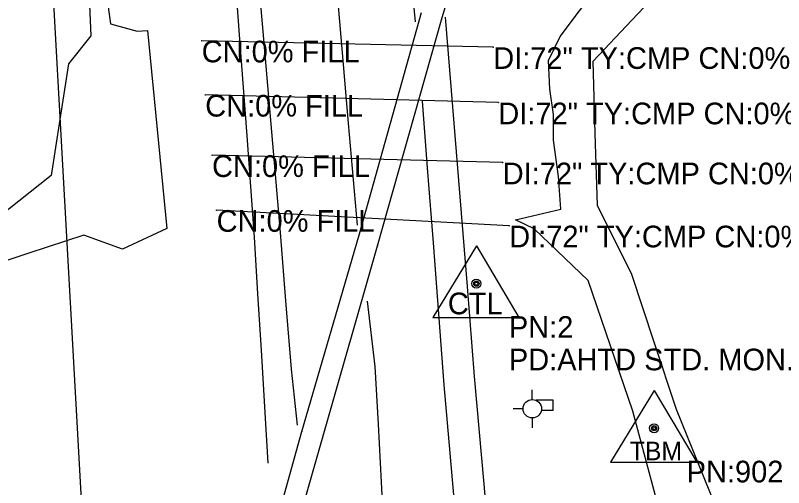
# Model space of a CAD drawing. Extents: x 929765 to 934279, y 1533086 to 1541189.
# Drawn here: x 931934.2 to 932111.4, y 1537318.7 to 1537427.6 of the extents above; entities that cross this region are included whole.
import ezdxf

# ---------------------------------------------------------------- set-up
doc = ezdxf.new("R2010")
doc.units = 0
for name, color, linetype in [('S_CROSS_DRAIN', 7, 'Continuous'), ('S_CROSS_DRAIN_ANNOT', 7, 'Continuous'), ('S_DITCHLINE', 7, 'Continuous'), ('S_DRG_PT_SYM', 7, 'Continuous'), ('S_EDGE_PAVEMENT', 7, 'Continuous'), ('S_MSC_PT_SYM', 7, 'Continuous'), ('S_PAVEMENT_CROWN', 7, 'Continuous'), ('S_PRIMARY_CTL', 7, 'Continuous'), ('S_PRIMARY_CTL_ANNOT', 7, 'Continuous'), ('S_RAILROAD', 7, 'Continuous'), ('S_SANITARY_SEWER', 7, 'Continuous'), ('S_SHOULDER', 7, 'Continuous')]:
    doc.layers.add(name, color=color, linetype=linetype)

msp = doc.modelspace()

# ---------------------------------------------------------------- linework, layer by layer
at = {"layer": 'S_CROSS_DRAIN'}
for p, q in [((932044.4, 1537420.25), (931977.17, 1537421.75)), ((932045.58, 1537407.47), (931977.98, 1537409.25)), ((932046.59, 1537393.62), (931979.56, 1537395.31)), ((932048.08, 1537379.08), (931980.61, 1537382.67))]:
    msp.add_line(p, q, dxfattribs=at)
at = {"layer": 'S_DITCHLINE'}
for points in [[(932085.78, 1537301.84), (932081.18, 1537319.05), (932076.57, 1537336.26), (932071.43, 1537351.35), (932066.29, 1537366.45), (932053.86, 1537378.37), (932049.5, 1537380.42), (932059.98, 1537382.88), (932059.48, 1537390.45), (932058.32, 1537398.79), (932058.33, 1537404.72), (932057.44, 1537410.6), (932057.14, 1537417.22), (932059.87, 1537422.73), (932068.73, 1537434.65), (932077.6, 1537446.56), (932085.12, 1537457.75), (932092.64, 1537468.94), (932092.11, 1537482.59), (932096.23, 1537495.57), (932101.45, 1537495.39), (932102.69, 1537491.18), (932106.29, 1537496.21)], [(932126.62, 1537258.44), (932108.91, 1537270.62), (932105.45, 1537284.68), (932101.98, 1537298.75), (932094.32, 1537317.71), (932086.66, 1537336.67), (932081.51, 1537352.24), (932076.37, 1537367.8), (932068.43, 1537383.73), (932067.92, 1537400.37), (932067.42, 1537417), (932077.7, 1537427.87), (932087.98, 1537438.73), (932101.66, 1537459.25), (932108.63, 1537471.21), (932115.61, 1537483.17), (932113.54, 1537495.88)], [(931960.73, 1537473.11), (931955.67, 1537459.62), (931950.61, 1537446.13), (931951.63, 1537422.85), (931946.42, 1537416.45), (931944.44, 1537403.55), (931942.46, 1537390.65), (931930.06, 1537380.86), (931917.67, 1537371.06), (931905.8, 1537349.22), (931891.3, 1537336.47)], [(931964.13, 1537470.78), (931958.69, 1537458.85), (931953.25, 1537446.93), (931956.11, 1537425.64), (931962.3, 1537423.93), (931964.69, 1537424.11), (931966.9, 1537401.27), (931969.1, 1537378.44), (931958.88, 1537373.67), (931949.96, 1537376.9), (931937.32, 1537372.75), (931924.68, 1537368.59), (931916.88, 1537353.63), (931909.08, 1537338.66), (931901.6, 1537326.5), (931894.11, 1537314.34), (931873.82, 1537300.85), (931853.53, 1537287.36), (931835.12, 1537272.97), (931824.41, 1537264.81), (931813.7, 1537256.65), (931802.99, 1537248.49), (931792.29, 1537240.33), (931772.04, 1537229.23)]]:
    msp.add_lwpolyline(points, dxfattribs=at)
at = {"layer": 'S_DRG_PT_SYM'}
for points in [[(931977.17, 1537421.75), (931977.17, 1537421.8), (931977.17, 1537421.75), (931977.12, 1537421.75), (931977.17, 1537421.75), (931977.17, 1537421.7), (931977.17, 1537421.75), (931977.22, 1537421.75)], [(932044.4, 1537420.25), (932044.4, 1537420.3), (932044.4, 1537420.25), (932044.35, 1537420.25), (932044.4, 1537420.25), (932044.4, 1537420.2), (932044.4, 1537420.25), (932044.45, 1537420.25)], [(931977.98, 1537409.25), (931977.98, 1537409.3), (931977.98, 1537409.25), (931977.93, 1537409.25), (931977.98, 1537409.25), (931977.98, 1537409.2), (931977.98, 1537409.25), (931978.03, 1537409.25)], [(932045.58, 1537407.47), (932045.58, 1537407.52), (932045.58, 1537407.47), (932045.53, 1537407.47), (932045.58, 1537407.47), (932045.58, 1537407.42), (932045.58, 1537407.47), (932045.63, 1537407.47)], [(931979.56, 1537395.31), (931979.56, 1537395.36), (931979.56, 1537395.31), (931979.51, 1537395.31), (931979.56, 1537395.31), (931979.56, 1537395.26), (931979.56, 1537395.31), (931979.61, 1537395.31)], [(932046.59, 1537393.62), (932046.59, 1537393.67), (932046.59, 1537393.62), (932046.54, 1537393.62), (932046.59, 1537393.62), (932046.59, 1537393.57), (932046.59, 1537393.62), (932046.64, 1537393.62)], [(931980.61, 1537382.67), (931980.61, 1537382.72), (931980.61, 1537382.67), (931980.56, 1537382.67), (931980.61, 1537382.67), (931980.61, 1537382.62), (931980.61, 1537382.67), (931980.66, 1537382.67)], [(932048.08, 1537379.08), (932048.08, 1537379.13), (932048.08, 1537379.08), (932048.03, 1537379.08), (932048.08, 1537379.08), (932048.08, 1537379.03), (932048.08, 1537379.08), (932048.13, 1537379.08)]]:
    msp.add_lwpolyline(points, dxfattribs=at)
at = {"layer": 'S_EDGE_PAVEMENT'}
for points in [[(931999.26, 1537333.05), (931997.86, 1537345.98), (931996.59, 1537361.76), (931995.32, 1537377.53), (931993.34, 1537400.7), (931991.36, 1537423.88), (931989.38, 1537447.05), (931987.39, 1537470.22), (931985.33, 1537491.8), (931983.28, 1537513.38), (931981.22, 1537534.96), (931979.16, 1537556.54)], [(932026.51, 1537426.11), (932024.2, 1537450.08), (932021.89, 1537474.04), (932020.58, 1537486.58), (932019.27, 1537499.11), (932019.09, 1537507.16)], [(932059.21, 1537034.36), (932058.05, 1537048.52), (932056.89, 1537062.69), (932055.72, 1537076.85), (932054.56, 1537091.01), (932053.08, 1537108.03), (932051.6, 1537125.05), (932050.12, 1537142.07), (932048.64, 1537159.08), (932046.94, 1537178.95), (932045.24, 1537198.83), (932043.54, 1537218.7), (932041.84, 1537238.57), (932040.71, 1537252.26), (932039.58, 1537265.94), (932038.44, 1537279.63), (932037.31, 1537293.31), (932035.21, 1537317.83), (932033.1, 1537342.36), (932031.84, 1537358.72), (932030.59, 1537375.09), (932029.34, 1537391.46), (932028.08, 1537407.83)]]:
    msp.add_lwpolyline(points, dxfattribs=at)
at = {"layer": 'S_MSC_PT_SYM'}
for points in [[(932032.49, 1537426.55), (932032.49, 1537426.6), (932032.49, 1537426.55), (932032.44, 1537426.55), (932032.49, 1537426.55), (932032.49, 1537426.5), (932032.49, 1537426.55), (932032.54, 1537426.55)], [(932013.4, 1537376.69), (932013.4, 1537376.74), (932013.4, 1537376.69), (932013.35, 1537376.69), (932013.4, 1537376.69), (932013.4, 1537376.64), (932013.4, 1537376.69), (932013.45, 1537376.69)], [(932017.74, 1537374.41), (932017.74, 1537374.46), (932017.74, 1537374.41), (932017.69, 1537374.41), (932017.74, 1537374.41), (932017.74, 1537374.36), (932017.74, 1537374.41), (932017.79, 1537374.41)], [(932000.29, 1537331.57), (932000.29, 1537331.62), (932000.29, 1537331.57), (932000.24, 1537331.57), (932000.29, 1537331.57), (932000.29, 1537331.52), (932000.29, 1537331.57), (932000.34, 1537331.57)], [(932005.02, 1537330.1), (932005.02, 1537330.15), (932005.02, 1537330.1), (932004.97, 1537330.1), (932005.02, 1537330.1), (932005.02, 1537330.05), (932005.02, 1537330.1), (932005.07, 1537330.1)]]:
    msp.add_lwpolyline(points, dxfattribs=at)
at = {"layer": 'S_PAVEMENT_CROWN'}
for points in [[(932013.1, 1537379.23), (932011.05, 1537402.7), (932008.99, 1537426.17), (932006.94, 1537449.63), (932004.88, 1537473.1), (932002.67, 1537494.31), (932000.45, 1537515.52), (931998.24, 1537536.73), (931996.02, 1537557.94)], [(932041.76, 1537037.1), (932040.61, 1537050.43), (932039.45, 1537063.77), (932038.3, 1537077.1), (932037.14, 1537090.44), (932035.75, 1537107.51), (932034.36, 1537124.59), (932032.97, 1537141.66), (932031.58, 1537158.74), (932029.79, 1537178.36), (932027.99, 1537197.98), (932026.19, 1537217.6), (932024.39, 1537237.22), (932023.31, 1537251.24), (932022.23, 1537265.26), (932021.15, 1537279.28), (932020.07, 1537293.3), (932019.35, 1537306.62), (932018.64, 1537319.95), (932017.92, 1537333.27), (932017.2, 1537346.6), (932015.42, 1537361.67)]]:
    msp.add_lwpolyline(points, dxfattribs=at)
at = {"layer": 'S_PRIMARY_CTL'}
for p, q in [((932040.51, 1537374.41), (932030.48, 1537357.9)), ((932040.51, 1537374.41), (932050.34, 1537357.9)), ((932030.48, 1537357.9), (932050.34, 1537357.9)), ((932081.51, 1537341.06), (932071.48, 1537324.54)), ((932081.51, 1537341.06), (932091.33, 1537324.54)), ((932071.48, 1537324.54), (932091.33, 1537324.54))]:
    msp.add_line(p, q, dxfattribs=at)
for centre, radius in [((932040.51, 1537365.71), 1.04), ((932040.51, 1537365.71), 0.609), ((932040.51, 1537365.71), 0.344), ((932081.51, 1537332.36), 1.04), ((932081.51, 1537332.36), 0.609), ((932081.51, 1537332.36), 0.344)]:
    msp.add_circle(centre, radius, dxfattribs=at)
at = {"layer": 'S_RAILROAD'}
for p, q in [((932032.49, 1537426.55), (932048.31, 1537482.23)), ((932013.4, 1537376.69), (932027.87, 1537428.26)), ((932017.74, 1537374.41), (932032.49, 1537426.55)), ((932000.29, 1537331.57), (932013.4, 1537376.69)), ((932005.02, 1537330.1), (932017.74, 1537374.41)), ((932053.4, 1537338.96), (932053.4, 1537341.21)), ((932058.21, 1537338.8), (932054.33, 1537338.8)), ((932058.21, 1537336.48), (932058.21, 1537338.8)), ((932051.31, 1537336.83), (932048.99, 1537336.83)), ((932058.21, 1537336.48), (932055.5, 1537336.48)), ((932053.48, 1537332.41), (932053.48, 1537334.73)), ((931989.67, 1537294.03), (932000.29, 1537331.57)), ((931994.39, 1537292.75), (932005.02, 1537330.1))]:
    msp.add_line(p, q, dxfattribs=at)
msp.add_circle((932053.41, 1537336.85), 2.13, dxfattribs=at)
at = {"layer": 'S_SANITARY_SEWER'}
msp.add_line((931950.77, 1537292.06), (931940.09, 1537483.33), dxfattribs=at)
at = {"layer": 'S_SHOULDER'}
for points in [[(931992.49, 1537324.27), (931991.71, 1537337.31), (931990.93, 1537350.35), (931990.15, 1537363.39), (931989.37, 1537376.43), (931987.64, 1537399.77), (931985.9, 1537423.12), (931984.16, 1537446.46), (931982.42, 1537469.81), (931981.22, 1537485.1), (931980.01, 1537500.39), (931979.72, 1537501.28)], [(932065.34, 1537035.86), (932064.27, 1537049.8), (932063.21, 1537063.74), (932062.14, 1537077.68), (932061.08, 1537091.63), (932059.66, 1537108.77), (932058.23, 1537125.91), (932056.81, 1537143.06), (932055.39, 1537160.2), (932053.73, 1537179.84), (932052.07, 1537199.48), (932050.41, 1537219.11), (932048.75, 1537238.75), (932047.67, 1537252.72), (932046.6, 1537266.7), (932045.52, 1537280.67), (932044.45, 1537294.64), (932042.28, 1537319.47), (932040.11, 1537344.3), (932038.43, 1537365.02), (932036.75, 1537385.74), (932035.07, 1537406.47), (932033.39, 1537427.19)]]:
    msp.add_lwpolyline(points, dxfattribs=at)

# ---------------------------------------------------------------- texts
at = {"layer": 'S_CROSS_DRAIN_ANNOT'}
for s, p in [('CN:0% FILL', (931977.17, 1537416.75)), ('DI:72" TY:CMP CN:0% FILL LN:67\'', (932044.4, 1537415.25)), ('CN:0% FILL', (931977.98, 1537404.25)), ('DI:72" TY:CMP CN:0% FILL LN:68\'', (932045.58, 1537402.47)), ('CN:0% FILL', (931979.56, 1537390.31)), ('DI:72" TY:CMP CN:0% FILL LN:67\'', (932046.59, 1537388.62)), ('CN:0% FILL', (931980.61, 1537377.67)), ('DI:72" TY:CMP CN:0% FILL LN:68\'', (932048.08, 1537374.08))]:
    msp.add_text(s, height=5, dxfattribs=at).set_placement(p)
at = {"layer": 'S_PRIMARY_CTL'}
for s, height, p in [('CTL', 5, (932033.93, 1537358.64)), ('TBM', 4.287, (932075.86, 1537324.97))]:
    msp.add_text(s, height=height, rotation=360, dxfattribs=at).set_placement(p)
at = {"layer": 'S_PRIMARY_CTL_ANNOT'}
for s, p in [('PN:2', (932048.01, 1537353.21)), ('PD:AHTD STD. MON. STAMPED PN:2', (932048.01, 1537345.71)), ('PN:902', (932089.01, 1537319.86))]:
    msp.add_text(s, height=5, dxfattribs=at).set_placement(p)

doc.saveas('drawing.dxf')
